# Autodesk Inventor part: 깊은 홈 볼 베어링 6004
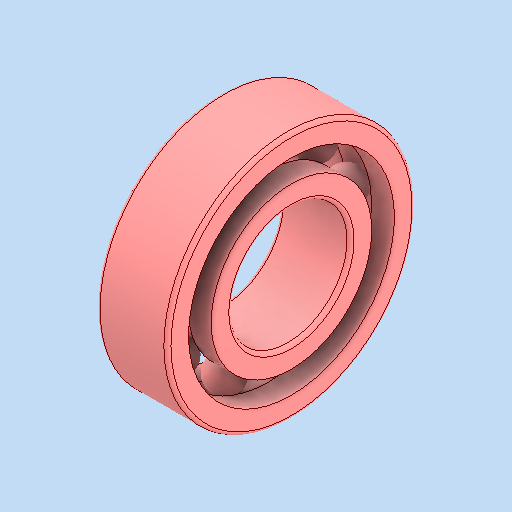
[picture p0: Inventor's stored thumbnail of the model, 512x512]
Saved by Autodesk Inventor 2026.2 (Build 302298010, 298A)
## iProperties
Created: 2026-03
Part Number: 깊은 홈 볼 베어링 6004
Material: 강철, 연강
Description: 깊은 그루브 볼 베어링
Document SubType Name: Modeling
Designer: PC-2-06
Density: 7.85 g/cm^3
Appearance: 기본값
Author: jhkim
Sending System: Autodesk Inventor 2026
Preprocessor: ST-DEVELOPER v20.1
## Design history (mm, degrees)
feature "Solid1"
feature "Solid1:1"
feature "Solid1:2"
feature "Solid1:3"
feature "Solid1:4"
feature "Solid1:5"
feature "Solid1:6"
feature "Solid1:7"
feature "Solid1:8"
feature "Solid1:9"
feature "Solid1:10"
node "솔리드1"
node "솔리드2"
node "솔리드3"
node "솔리드4"
node "솔리드5"
node "솔리드6"
node "솔리드7"
node "솔리드8"
node "솔리드9"
node "솔리드10"
node "솔리드11"
